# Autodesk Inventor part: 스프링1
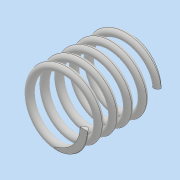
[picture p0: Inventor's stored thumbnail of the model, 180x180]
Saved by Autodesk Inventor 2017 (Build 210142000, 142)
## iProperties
Part Number: 스프링1
Material: 일반
Document SubType Name: Modeling
Designer: MRC
Density: 1 g/cm^3
Appearance: 기본값
Mass: 0.821961 g
Surface Area: 16.7185 cm^2
Volume: 0.821961 cm^3
Author: MRC
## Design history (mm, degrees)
sketch "스케치1"
  geometry: L1 (0, 0)-(0, 20.5); L2 (0, 0)-(8.5, 0); L3 (0, 20.5)-(8.5, 20.5); C1 r 1 at (8.5, 0)
  constraints: 6 end point, 2 horizontal, 1 centre point, 1 coincident, 1 parallel, 1 vertical
  dimensions: "d0" = 20.5 distance of L1.start L1.end (derived); "d1" = 17 diameter of L2.end L1; "d2" = 2 diameter of C1
feature "코일1" sketch "스케치1" pitch "d3" = 10; turns "d5" = 5; dims "d4" = 20.5 (= d0), "d6" = 0, angle "d7" = 90 deg, angle "d8" = 90 deg, "d9" = 0, "d10" = 0
sketch "스케치2"
  geometry: L1 (20.5, 14.331)-(0, 14.331); L2 (0, 14.331)-(0, -14.331); L3 (0, -14.331)-(20.5, -14.331); L4 (20.5, -14.331)-(20.5, 14.331); 2 further points
  constraints: 8 end point, 2 parallel, 1 coincident, 1 horizontal, 1 midpoint, 1 perpendicular
  dimensions: "d11" = 28.66142 distance of L3.end L1.start; "d12" = 20.5 distance of L2.end L3.end (= d0)
extrude "돌출1" sketch "스케치2" stored distance "d13" = 0; taper "d14" = 0 deg
node "솔리드1"
